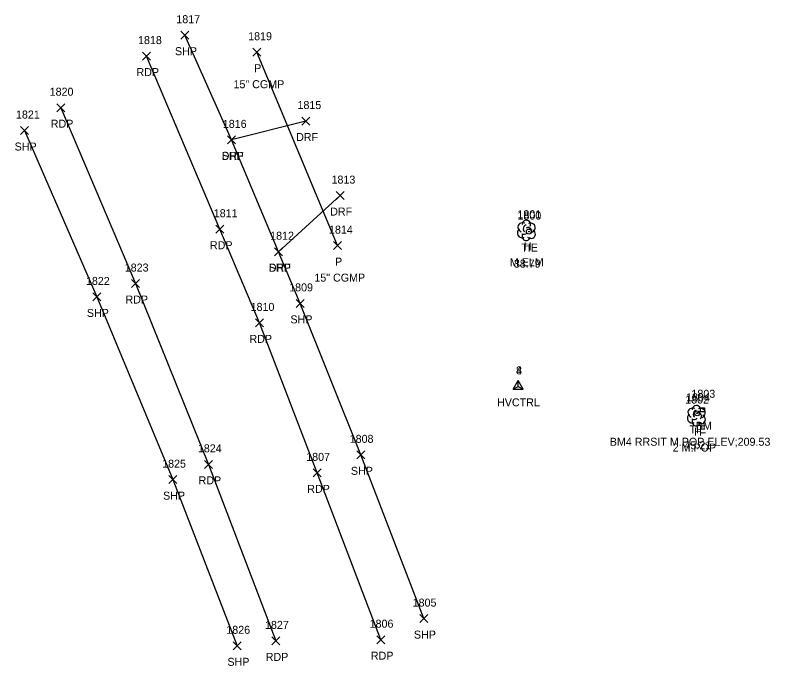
# Model space of a CAD drawing. Extents: x 1443960 to 1446865, y 610387 to 616706.
# Drawn here: x 1446358.8 to 1446547.5, y 612534 to 612696.8 of the extents above; entities that cross this region are included whole.
import ezdxf

# ---------------------------------------------------------------- set-up
doc = ezdxf.new("R2010")
doc.units = 0
for name, color, linetype in [('C_A', 7, 'Continuous'), ('C_C', 7, 'Continuous'), ('C_I', 7, 'Continuous'), ('CBP', 7, 'Continuous'), ('CPBM', 7, 'Continuous'), ('CPSM', 7, 'Continuous'), ('D_A', 7, 'Continuous'), ('D_C', 7, 'Continuous'), ('D_I', 7, 'Continuous'), ('D_TIC', 7, 'Continuous'), ('DCP', 7, 'Continuous'), ('L_A', 7, 'Continuous'), ('L_C', 7, 'Continuous'), ('L_I', 7, 'Continuous'), ('LTD', 7, 'Continuous'), ('P_A', 7, 'Continuous'), ('P_I', 7, 'Continuous'), ('P_TIC', 7, 'Continuous'), ('PET', 7, 'Continuous'), ('PSP', 7, 'Continuous'), ('R_A', 7, 'Continuous'), ('R_I', 7, 'Continuous'), ('R_TIC', 7, 'Continuous'), ('RDF', 7, 'Continuous')]:
    doc.layers.add(name, color=color, linetype=linetype)

msp = doc.modelspace()

# ---------------------------------------------------------------- linework, layer by layer
at = {"layer": 'CBP'}
for centre, radius in [((1446487.26, 612642.64), 0.625), ((1446487.26, 612642.64), 0.0833), ((1446529.32, 612597.19), 0.625), ((1446529.32, 612597.19), 0.0833)]:
    msp.add_circle(centre, radius, dxfattribs=at)
at = {"layer": 'CPBM'}
for p, q in [((1446530.16, 612597.58), (1446530.16, 612598.58)), ((1446530.16, 612598.58), (1446531.16, 612598.58)), ((1446531.16, 612598.58), (1446531.16, 612597.58)), ((1446531.16, 612597.58), (1446530.16, 612597.58)), ((1446530.67, 612598.08), (1446530.67, 612598.08)), ((1446530.67, 612598.08), (1446530.67, 612598.08))]:
    msp.add_line(p, q, dxfattribs=at)
at = {"layer": 'CPSM'}
for p, q in [((1446483.34, 612603.21), (1446484.59, 612605.38)), ((1446483.34, 612603.21), (1446484.6, 612603.93)), ((1446483.36, 612603.21), (1446484.61, 612605.38)), ((1446483.36, 612603.21), (1446484.61, 612603.94)), ((1446485.84, 612603.21), (1446484.59, 612605.38)), ((1446484.6, 612603.93), (1446484.59, 612605.38)), ((1446484.6, 612603.93), (1446484.6, 612603.93)), ((1446484.6, 612603.93), (1446485.84, 612603.21)), ((1446485.86, 612603.21), (1446484.61, 612605.38)), ((1446484.61, 612603.94), (1446484.61, 612605.38)), ((1446484.61, 612603.94), (1446484.61, 612603.94)), ((1446484.61, 612603.94), (1446485.86, 612603.21)), ((1446483.34, 612603.21), (1446485.84, 612603.21)), ((1446483.36, 612603.21), (1446485.86, 612603.21))]:
    msp.add_line(p, q, dxfattribs=at)
at = {"layer": 'D_TIC'}
for points in [[(1446418.21, 612686.51), (1446420.21, 612688.51)], [(1446420.21, 612686.51), (1446418.21, 612688.51)], [(1446438.42, 612638.13), (1446440.42, 612640.13)], [(1446440.42, 612638.13), (1446438.42, 612640.13)]]:
    msp.add_lwpolyline(points, dxfattribs=at)
at = {"layer": 'DCP'}
msp.add_lwpolyline([(1446439.42, 612639.13), (1446419.21, 612687.51)], dxfattribs=at)
at = {"layer": 'LTD'}
for p, q in [((1446486.59, 612642.99), (1446486.59, 612642.99)), ((1446486.59, 612642.99), (1446486.59, 612642.99)), ((1446529.1, 612596.64), (1446529.1, 612596.64)), ((1446529.1, 612596.64), (1446529.1, 612596.64))]:
    msp.add_line(p, q, dxfattribs=at)
for centre in [(1446486.64, 612644.42), (1446529.15, 612598.08)]:
    msp.add_arc(centre, 1.05, 335.5272, 180.9563, dxfattribs=at)
for centre, major_axis, ratio, start_param, end_param in [((1446485.8, 612643.65), (1.21, -0.51), 0.895232, 1.570796, 4.712389), ((1446486.38, 612643.45), (-0.208, -0.792), 0.645439, 3.141593, 6.283185), ((1446487.09, 612642.82), (-0.5, 0.667), 0.989748, 3.141593, 6.283185), ((1446487.63, 612643.57), (-1.14, -0.48), 0.949671, 1.570796, 4.712389), ((1446485.51, 612642.28), (0.58, -1.04), 0.959034, 3.141593, 6.283185), ((1446486.59, 612641.49), (0.26, 1.06), 0.942809, 1.570796, 4.712389), ((1446486.13, 612642.24), (-0.625, -0.083), 0.423636, 0, 3.141593), ((1446487.59, 612642.16), (-1.09, 0.79), 0.841452, 1.570796, 4.712389), ((1446528.31, 612597.31), (1.21, -0.51), 0.895232, 1.570796, 4.712389), ((1446530.14, 612597.23), (-1.14, -0.48), 0.949671, 1.570796, 4.712389), ((1446528.02, 612595.94), (0.58, -1.04), 0.959034, 3.141593, 6.283185), ((1446528.89, 612597.1), (-0.208, -0.792), 0.645439, 3.141593, 6.283185), ((1446529.6, 612596.48), (-0.5, 0.667), 0.989748, 3.141593, 6.283185), ((1446530.1, 612595.81), (-1.09, 0.79), 0.841452, 1.570796, 4.712389), ((1446529.1, 612595.14), (0.26, 1.06), 0.942809, 1.570796, 4.712389), ((1446528.64, 612595.89), (-0.625, -0.083), 0.423636, 0, 3.141593)]:
    msp.add_ellipse(centre, major_axis=major_axis, ratio=ratio, start_param=start_param, end_param=end_param, dxfattribs=at)
at = {"layer": 'P_TIC'}
for points in [[(1446400.25, 612690.77), (1446402.25, 612692.77)], [(1446402.25, 612690.77), (1446400.25, 612692.77)], [(1446390.67, 612685.54), (1446392.67, 612687.54)], [(1446392.67, 612685.54), (1446390.67, 612687.54)], [(1446369.24, 612672.63), (1446371.24, 612674.63)], [(1446371.24, 612672.63), (1446369.24, 612674.63)], [(1446360.16, 612666.92), (1446362.16, 612668.92)], [(1446362.16, 612666.92), (1446360.16, 612668.92)], [(1446411.92, 612664.59), (1446413.92, 612666.59)], [(1446413.92, 612664.59), (1446411.92, 612666.59)], [(1446409.04, 612642.24), (1446411.04, 612644.24)], [(1446411.04, 612642.24), (1446409.04, 612644.24)], [(1446423.7, 612636.61), (1446425.7, 612638.61)], [(1446425.7, 612636.61), (1446423.7, 612638.61)], [(1446387.92, 612628.65), (1446389.92, 612630.65)], [(1446389.92, 612628.65), (1446387.92, 612630.65)], [(1446378.22, 612625.3), (1446380.22, 612627.3)], [(1446380.22, 612625.3), (1446378.22, 612627.3)], [(1446429.11, 612623.69), (1446431.11, 612625.69)], [(1446431.11, 612623.69), (1446429.11, 612625.69)], [(1446418.91, 612618.81), (1446420.91, 612620.81)], [(1446420.91, 612618.81), (1446418.91, 612620.81)], [(1446444.23, 612585.81), (1446446.23, 612587.81)], [(1446446.23, 612585.81), (1446444.23, 612587.81)], [(1446406.2, 612583.43), (1446408.2, 612585.43)], [(1446408.2, 612583.43), (1446406.2, 612585.43)], [(1446433.36, 612581.3), (1446435.36, 612583.3)], [(1446435.36, 612581.3), (1446433.36, 612583.3)], [(1446397.28, 612579.6), (1446399.28, 612581.6)], [(1446399.28, 612579.6), (1446397.28, 612581.6)], [(1446459.97, 612544.85), (1446461.97, 612546.85)], [(1446461.97, 612544.85), (1446459.97, 612546.85)], [(1446413.36, 612538.04), (1446415.36, 612540.04)], [(1446415.36, 612538.04), (1446413.36, 612540.04)], [(1446422.98, 612539.27), (1446424.98, 612541.27)], [(1446424.98, 612539.27), (1446422.98, 612541.27)], [(1446449.26, 612539.57), (1446451.26, 612541.57)], [(1446451.26, 612539.57), (1446449.26, 612541.57)]]:
    msp.add_lwpolyline(points, dxfattribs=at)
at = {"layer": 'PET'}
for points in [[(1446450.26, 612540.57), (1446434.36, 612582.3), (1446419.91, 612619.81), (1446410.04, 612643.24), (1446391.67, 612686.54)], [(1446370.24, 612673.63), (1446388.92, 612629.65), (1446407.2, 612584.43), (1446423.98, 612540.27)]]:
    msp.add_lwpolyline(points, dxfattribs=at)
at = {"layer": 'PSP'}
for points in [[(1446460.97, 612545.85), (1446445.23, 612586.81), (1446430.11, 612624.69), (1446424.7, 612637.61), (1446412.92, 612665.59), (1446401.25, 612691.77)], [(1446361.16, 612667.92), (1446379.22, 612626.3), (1446398.28, 612580.6), (1446414.36, 612539.04)]]:
    msp.add_lwpolyline(points, dxfattribs=at)
at = {"layer": 'R_TIC'}
for points in [[(1446430.53, 612669.3), (1446432.53, 612671.3)], [(1446432.53, 612669.3), (1446430.53, 612671.3)], [(1446411.92, 612664.59), (1446413.92, 612666.59)], [(1446413.92, 612664.59), (1446411.92, 612666.59)], [(1446439.04, 612650.65), (1446441.04, 612652.65)], [(1446441.04, 612650.65), (1446439.04, 612652.65)], [(1446423.7, 612636.61), (1446425.7, 612638.61)], [(1446425.7, 612636.61), (1446423.7, 612638.61)]]:
    msp.add_lwpolyline(points, dxfattribs=at)
at = {"layer": 'RDF'}
for points in [[(1446431.53, 612670.3), (1446412.92, 612665.59)], [(1446424.7, 612637.61), (1446440.04, 612651.65)]]:
    msp.add_lwpolyline(points, dxfattribs=at)

# ---------------------------------------------------------------- texts
at = {"layer": 'C_A'}
for s, p in [('TIE', (1446485.34, 612637.64)), ('HVCTRL', (1446479.29, 612598.93)), ('HVCTRL', (1446479.3, 612598.94)), ('BM', (1446528.98, 612593.08)), ('TIE', (1446527.4, 612592.19))]:
    msp.add_text(s, height=2, dxfattribs=at).set_placement(p)
at = {"layer": 'C_C'}
for s, p in [('38.79', (1446483.5, 612633.64)), ('BM4 RRSIT M.POP ELEV;209.53', (1446507.48, 612589.08)), ('45.21', (1446526.14, 612588.19))]:
    msp.add_text(s, height=2, dxfattribs=at).set_placement(p)
at = {"layer": 'C_I'}
for s, p in [('1800', (1446484.4, 612645.64)), ('4', (1446484.04, 612606.94)), ('8', (1446484.03, 612606.93)), ('1804', (1446526.55, 612600.19)), ('1803', (1446527.89, 612601.08))]:
    msp.add_text(s, height=2, dxfattribs=at).set_placement(p)
at = {"layer": 'D_A'}
for p in [(1446418.59, 612682.51), (1446438.8, 612634.13)]:
    msp.add_text('P', height=2, dxfattribs=at).set_placement(p)
at = {"layer": 'D_C'}
for p in [(1446413.42, 612678.51), (1446433.63, 612630.13)]:
    msp.add_text('15" CGMP', height=2, dxfattribs=at).set_placement(p)
at = {"layer": 'D_I'}
for s, p in [('1819', (1446417.08, 612690.51)), ('1814', (1446437.29, 612642.13))]:
    msp.add_text(s, height=2, dxfattribs=at).set_placement(p)
at = {"layer": 'L_A'}
for p in [(1446486.02, 612637.99), (1446528.53, 612591.64)]:
    msp.add_text('H', height=2, dxfattribs=at).set_placement(p)
at = {"layer": 'L_C'}
for s, p in [('M.ELM', (1446482.49, 612633.99)), ('2 M.POP', (1446523.2, 612587.64))]:
    msp.add_text(s, height=2, dxfattribs=at).set_placement(p)
at = {"layer": 'L_I'}
for s, p in [('1801', (1446484.38, 612645.99)), ('1802', (1446526.33, 612599.64))]:
    msp.add_text(s, height=2, dxfattribs=at).set_placement(p)
at = {"layer": 'P_A'}
for s, p in [('SHP', (1446398.78, 612686.77)), ('RDP', (1446389.16, 612681.54)), ('RDP', (1446367.73, 612668.63)), ('SHP', (1446358.7, 612662.92)), ('SHP', (1446410.46, 612660.59)), ('RDP', (1446407.52, 612638.24)), ('SHP', (1446422.24, 612632.61)), ('RDP', (1446386.41, 612624.65)), ('SHP', (1446376.76, 612621.3)), ('SHP', (1446427.65, 612619.69)), ('RDP', (1446417.4, 612614.81)), ('SHP', (1446442.76, 612581.81)), ('RDP', (1446404.69, 612579.43)), ('SHP', (1446395.81, 612575.6)), ('RDP', (1446431.85, 612577.3)), ('SHP', (1446458.51, 612540.85)), ('SHP', (1446411.9, 612534.04)), ('RDP', (1446421.47, 612535.27)), ('RDP', (1446447.75, 612535.57))]:
    msp.add_text(s, height=2, dxfattribs=at).set_placement(p)
at = {"layer": 'P_I'}
for s, p in [('1817', (1446399.12, 612694.77)), ('1818', (1446389.55, 612689.54)), ('1820', (1446367.46, 612676.63)), ('1821', (1446359.04, 612670.92)), ('1816', (1446410.74, 612668.59)), ('1811', (1446408.48, 612646.24)), ('1812', (1446422.58, 612640.61)), ('1823', (1446386.23, 612632.65)), ('1822', (1446376.53, 612629.3)), ('1809', (1446427.33, 612627.69)), ('1810', (1446417.69, 612622.81)), ('1808', (1446442.46, 612589.81)), ('1824', (1446404.51, 612587.43)), ('1807', (1446431.59, 612585.3)), ('1825', (1446395.58, 612583.6)), ('1805', (1446458.2, 612548.85)), ('1806', (1446447.44, 612543.57)), ('1826', (1446411.62, 612542.04)), ('1827', (1446421.29, 612543.27))]:
    msp.add_text(s, height=2, dxfattribs=at).set_placement(p)
at = {"layer": 'R_A'}
for p in [(1446429.07, 612665.3), (1446410.46, 612660.59), (1446437.58, 612646.65), (1446422.24, 612632.61)]:
    msp.add_text('DRF', height=2, dxfattribs=at).set_placement(p)
at = {"layer": 'R_I'}
for s, p in [('1815', (1446429.41, 612673.3)), ('1816', (1446410.74, 612668.59)), ('1813', (1446437.92, 612654.65)), ('1812', (1446422.58, 612640.61))]:
    msp.add_text(s, height=2, dxfattribs=at).set_placement(p)

doc.saveas('drawing.dxf')
